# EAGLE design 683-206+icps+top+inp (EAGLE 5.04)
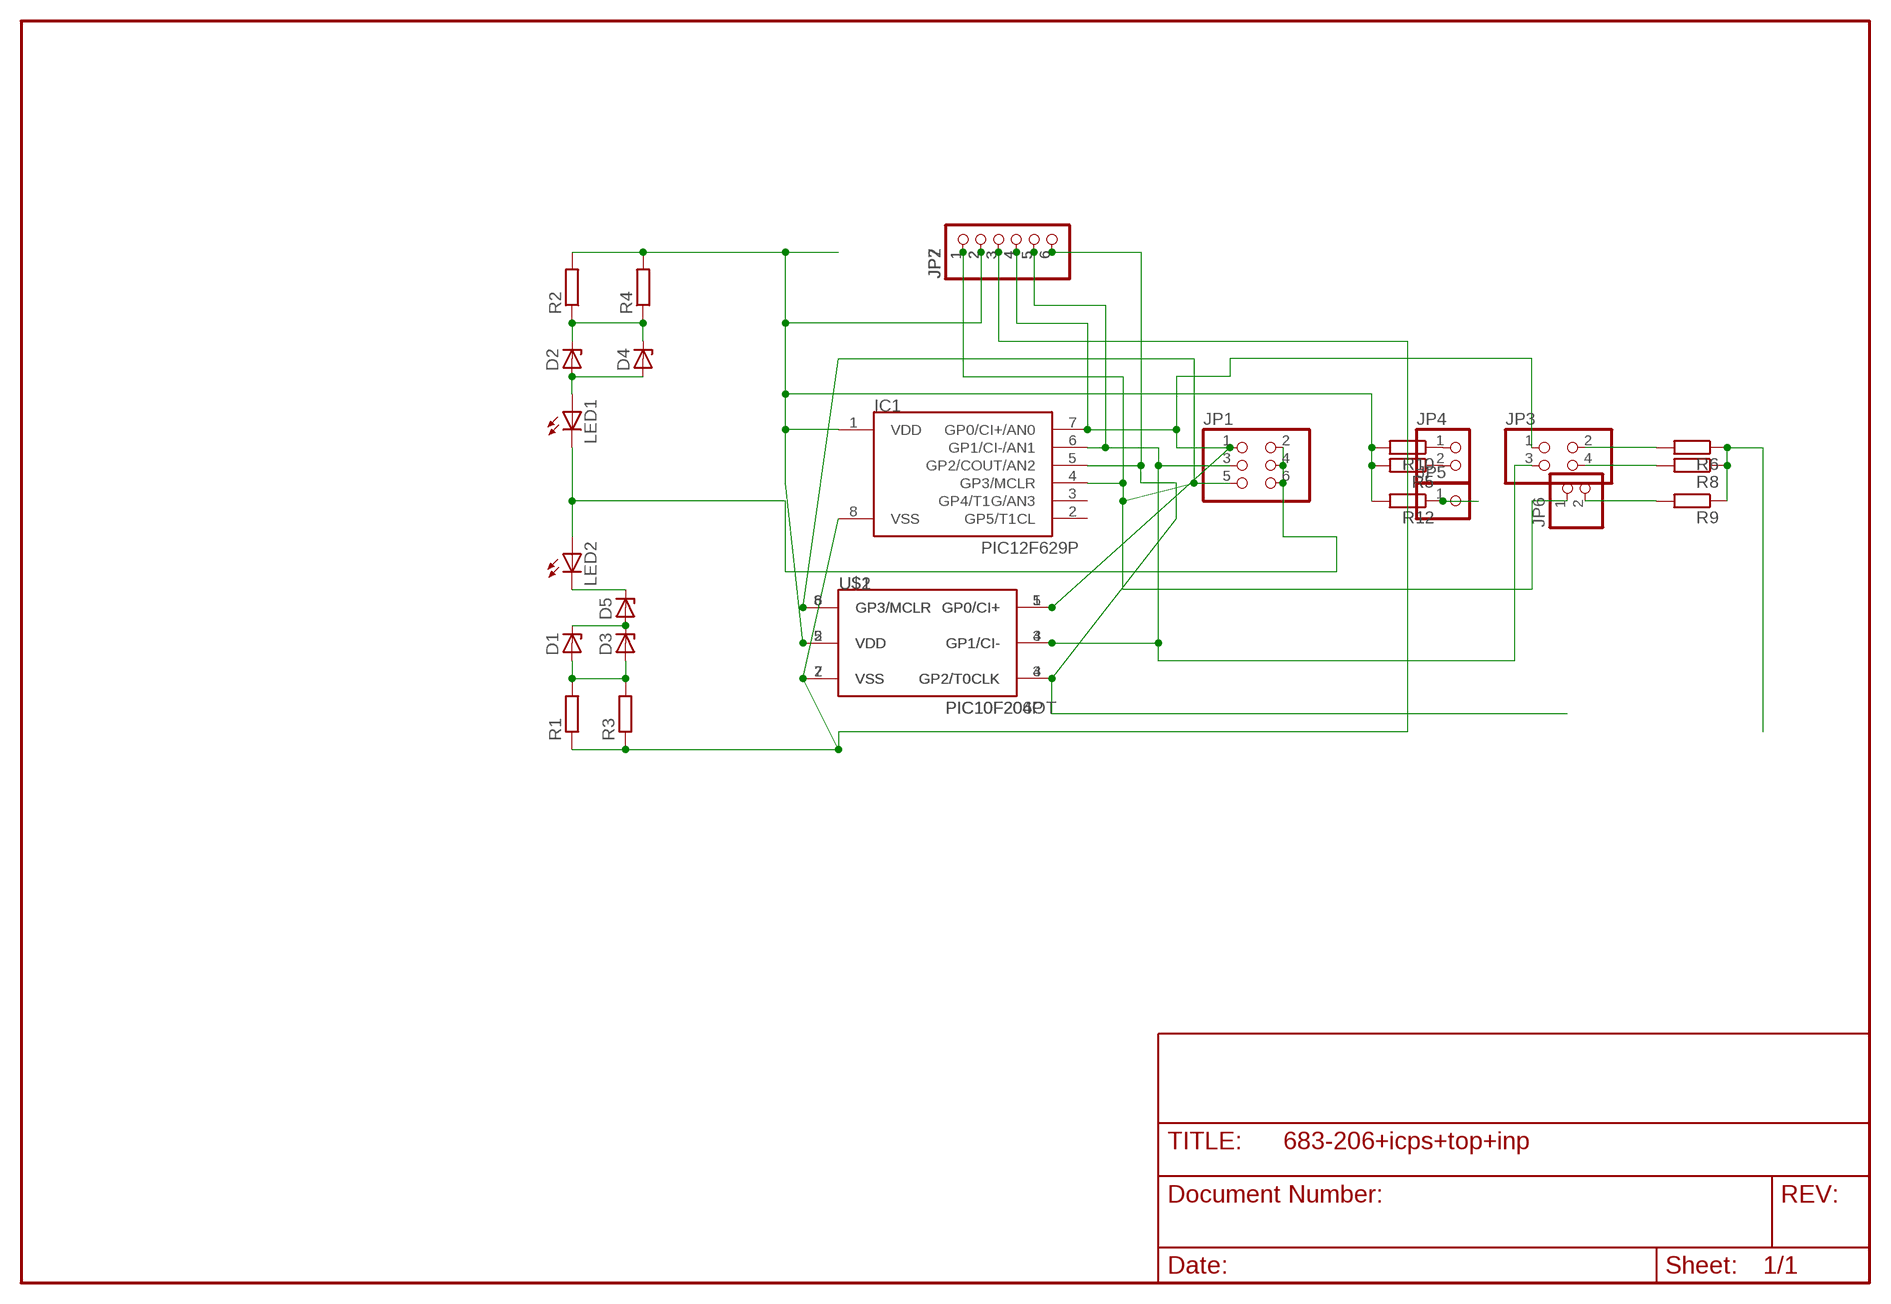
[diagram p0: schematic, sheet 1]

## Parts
D1  ZENER-DIODESOT23  [SOT23]
D2  ZENER-DIODESOT23  [SOT23]
D3  ZENER-DIODEZD-2.5  [ZDIO-2.5]
D4  ZENER-DIODEZD-2.5  [ZDIO-2.5]
D5  ZENER-DIODESOT23  [SOT23]
IC1  PIC12F629P  [DIL8]
JP1  PINHD-2X3  [2X03]
JP2  PINHD-1X6  [1X06]
JP3  PINHD-2X2  [2X02]
JP4  PINHD-1X2  [1X02]
JP5  PINHD-1X1  [1X01]
JP6  PINHD-1X2  [1X02]
JP7  PINHD-1X6  [1X06]
LED1  LED5MM  [LED5MM]
LED2  LED5MM  [LED5MM]
R1  R-EU_0204/2V  [0204V]
R2  R-EU_0204/2V  [0204V]
R3  R-EU_R1206  [R1206]
R4  R-EU_R1206  [R1206]
R5  R-EU_R1206  [R1206]
R6  R-EU_R1206  [R1206]
R8  R-EU_R1206  [R1206]
R9  R-EU_R1206  [R1206]
R10  R-EU_R1206  [R1206]
R12  R-EU_R1206  [R1206]
U$1  PIC10F206P  [DIL8]
U$2  PIC10F204OT  [SOT23-6]

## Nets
N$1: IC1.6(GP1/CI-/AN1) JP1.3 JP2.5 JP3.3 JP7.5 U$1.4(GP1/CI-) U$2.3(GP1/CI-)
N$2: D1.3(C) D3.C D5.1(A)
N$3: D1.1(A) D3.A R1.2 R3.2
N$4: JP1.2 JP1.4 JP1.6 LED1.K(C) LED2.A
N$5: IC1.8(VSS) JP2.3 JP7.3 R1.1 R3.1 U$1.7(VSS) U$2.2(VSS)
N$6: IC1.1(VDD) JP2.2 JP7.2 R2.2 R4.2 R5.2 R10.2 R12.2 U$1.2(VDD) U$2.5(VDD)
N$7: D2.1(A) D4.A LED1.A
N$8: D2.3(C) D4.C R2.1 R4.1
N$9: IC1.5(GP2/COUT/AN2) JP2.6 JP7.6 U$1.3(GP2/T0CLK) U$2.4(GP2/T0CLK)
N$10: IC1.4(GP3/MCLR) JP1.5 JP2.1 JP6.1 JP7.1 U$1.8(GP3/MCLR) U$2.6(GP3/MCLR)
N$11: D5.3(C) LED2.K(C)
N$13: IC1.7(GP0/CI+/AN0) JP1.1 JP2.4 JP3.1 JP7.4 U$1.5(GP0/CI+) U$2.1(GP0/CI+)
N$14: R6.1 R8.1 R9.1
N$15: JP4.2 R5.1
N$16: JP4.1 R10.1
N$18: JP5.1 R12.1
N$22: JP6.2 R9.2
N$24: JP3.4 R8.2
N$25: JP3.2 R6.2
Unconnected: IC1.2(GP5/T1CL) IC1.3(GP4/T1G/AN3)

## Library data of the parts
D1-D5 = diode-1:ZENER-DIODE: Z-Diode
IC1 = microchip-5:PIC12F6*: uPC nW 1k Program Flash memory 2x Timer Comparator 10b A/D converter/ 4xIN
JP1 = pinhead:PINHD-2X3: PIN HEADER
JP2 JP7 = pinhead:PINHD-1X6: PIN HEADER
JP3 = pinhead(2):PINHD-2X2: PIN HEADER
JP4 JP6 = pinhead(2):PINHD-1X2: PIN HEADER
JP5 = pinhead(2):PINHD-1X1: PIN HEADER
LED1 LED2 = led:LED: LED
R1-R6 R8-R10 R12 = rcl-2:R-EU_: RESISTOR, European symbol
U$1 U$2 = microchip-5:PIC10F2*: uPC nW 0,25/0,5k Program Flash memory Comparator

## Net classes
0 default: width 0.3 mm, drill 0.6 mm, clearance 0.2 mm
1 power: width 0.4 mm, drill 0.6 mm, clearance 0.2 mm

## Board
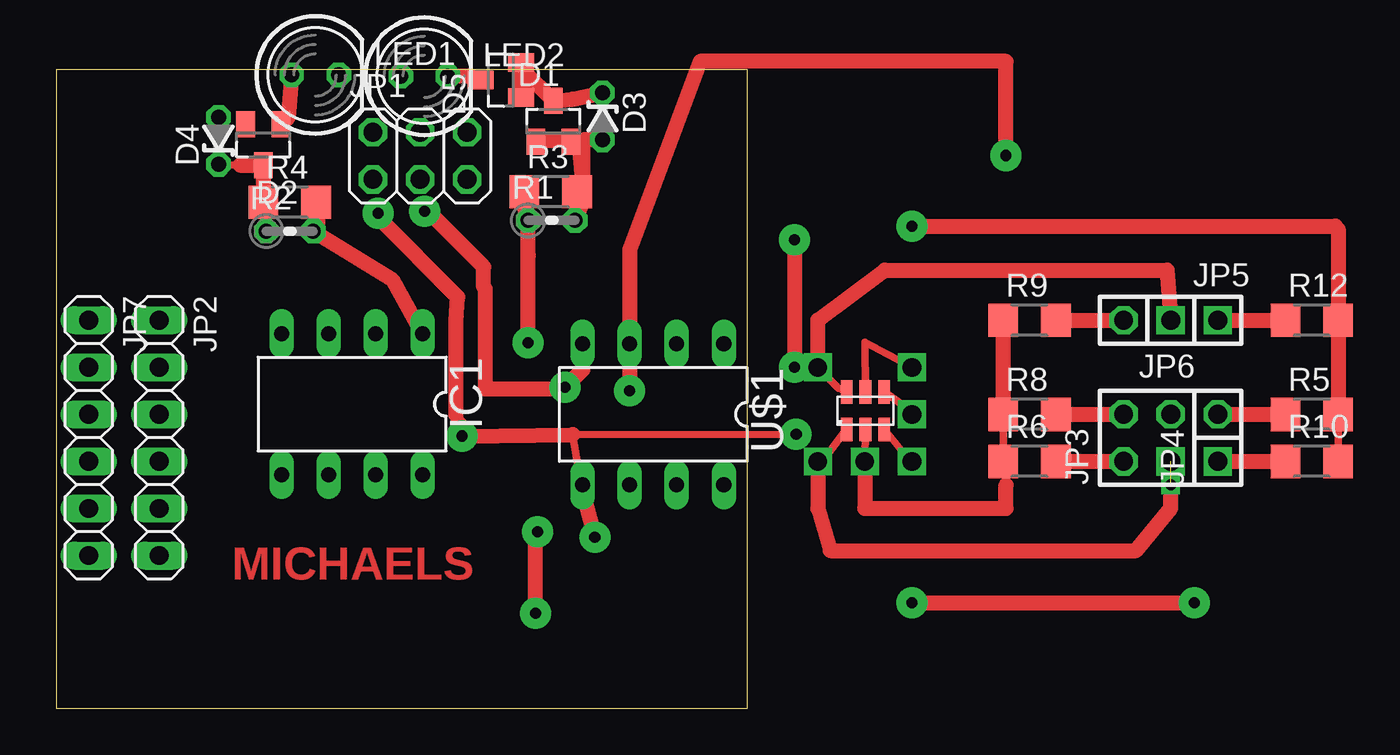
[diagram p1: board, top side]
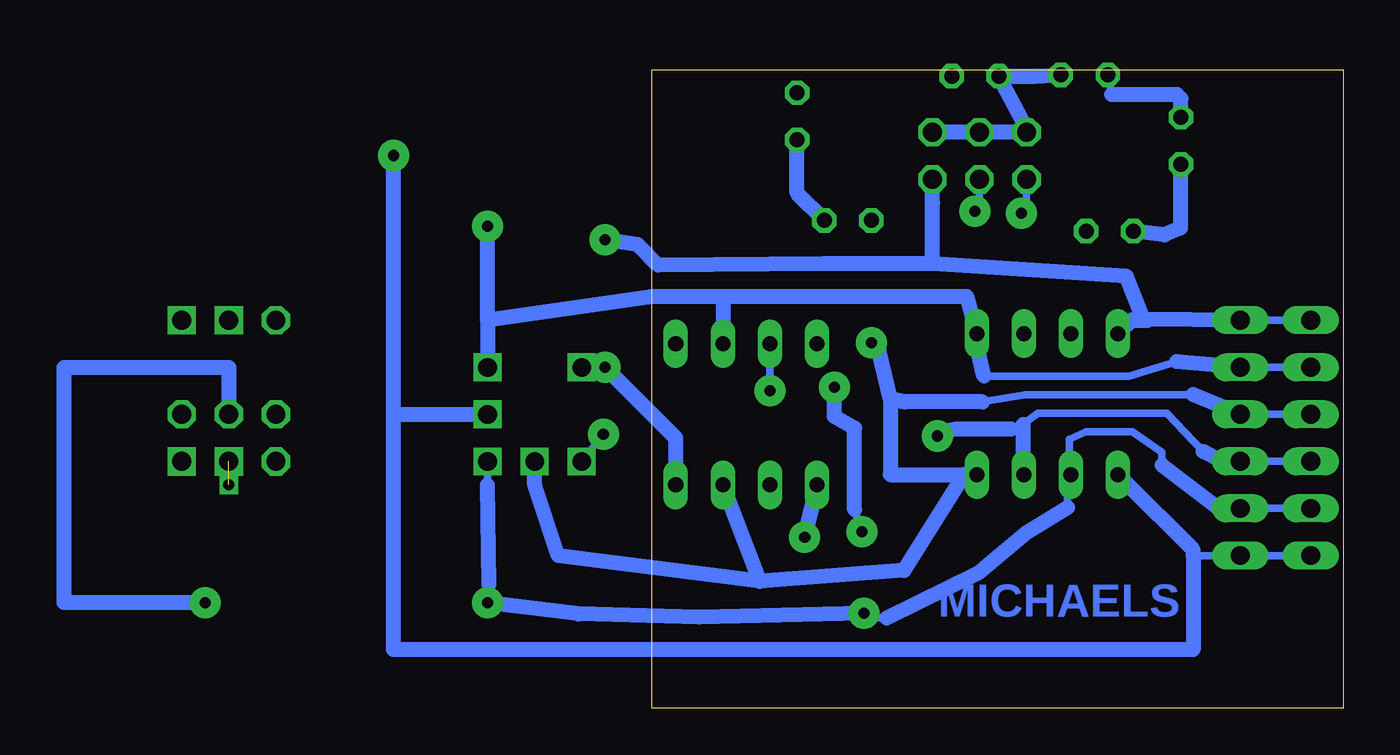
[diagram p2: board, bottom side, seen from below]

Size 37.3 x 34.48 mm. Coordinates in mm from the lower left corner, seen from the top.
Outline: 0,0 37.3,0 37.3,34.48 0,34.48 0,0
Copper layers (1*16): Top 0.035mm / dielectric 1.5mm / Bottom 0.035mm
Design rules "default": minimum track width 10mil, minimum drill 24mil, track to track 8mil, track to pad 8mil, pad to pad 8mil, via to via 8mil, smd to smd 8mil, copper to edge 40mil, drill to drill 8mil, minimum pad ring 10mil, minimum via ring 8mil, stop-mask expansion 4mil, vias tented up to drill 0mil, thermal gap 10mil

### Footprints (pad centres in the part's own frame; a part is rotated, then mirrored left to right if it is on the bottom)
SOT23 = smd 1 x 1.4: 1 -0.95,-1.1; 2 0.95,-1.1; 3 0,1.1
ZDIO-2.5 = drill 0.813 octagon: A 1.27,0; C -1.27,0
DIL8 = drill 0.813 long: 1 -3.81,-3.81; 2 -1.27,-3.81; 3 1.27,-3.81; 4 3.81,-3.81; 5 3.81,3.81; 6 1.27,3.81; 7 -1.27,3.81; 8 -3.81,3.81
2X03 = drill 1.016 octagon: 1 -2.54,-1.27; 2 -2.54,1.27; 3 0,-1.27; 4 0,1.27; 5 2.54,-1.27; 6 2.54,1.27
1X06 = drill 1.016 long: 1 -6.35,0; 2 -3.81,0; 3 -1.27,0; 4 1.27,0; 5 3.81,0; 6 6.35,0
2X02 = drill 1.016 square: 1 -1.27,-1.27 | drill 1.016 octagon: 2 -1.27,1.27; 3 1.27,-1.27; 4 1.27,1.27
1X02 = drill 1.016 square: 1 -1.27,0 | drill 1.016 octagon: 2 1.27,0
1X01 = drill 1.016 square: 1 0,0
LED5MM = drill 0.813 octagon: A -1.27,0; K 1.27,0
0204V = drill 0.813 octagon: 1 -1.27,0; 2 1.27,0
R1206 = smd 1.6 x 1.803: 1 -1.422,0; 2 1.422,0
SOT23-6 = smd 0.635 x 1.27: 1 -1.016,-1.016; 2 0,-1.016; 3 1.016,-1.016; 4 1.016,1.016; 5 0,1.016; 6 -1.016,1.016

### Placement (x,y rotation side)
D1  26.83,31.69 0 top
D2  11.17,30.41 180 top
D3  29.48,31.96 270 top
D4  8.75,30.63 90 top
D5  23.99,33.92 90 top
IC1  15.96,16.42 180 top
JP1  19.63,29.82 0 top
JP2  5.55,14.6 270 top
JP3  58.89,14.6 90 top  (outside the outline)
JP4  62.7,14.6 90 top  (outside the outline)
JP5  62.7,20.95 0 top  (outside the outline)
JP6  58.89,20.95 180 top  (outside the outline)
JP7  1.74,14.6 270 top
LED1  13.97,34.19 0 top
LED2  19.86,34.12 0 top
R1  26.74,26.33 0 top
R2  12.6,25.76 0 top
R3  26.69,27.88 0 top
R4  12.6,27.32 0 top
R5  67.78,15.87 0 top  (outside the outline)
R6  52.54,13.33 0 top  (outside the outline)
R8  52.54,15.87 0 top  (outside the outline)
R9  52.54,20.95 0 top  (outside the outline)
R10  67.78,13.33 0 top  (outside the outline)
R12  67.78,20.95 0 top  (outside the outline)
U$1  32.22,15.87 180 top
U$2  43.68,16.07 0 top  (outside the outline)

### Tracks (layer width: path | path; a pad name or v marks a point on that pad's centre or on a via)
N$1  (via drill 0.6 pad 1.68, 1)
  Top 0.406: U$2.3 45.7,13.82 v46.19,13.33 | 25.87,9.23 v25.97,9.53 | v27.47,17.33 27.37,17.23 | 20.07,26.83 v19.87,26.83 | 23.17,22.64 23.07,22.74
  Top 0.813: 23.17,22.64 23.17,17.23 27.37,17.23 | v25.87,5.13 25.87,9.23 | v46.19,5.71 v61.43,5.71 | U$1.4 28.41,18.27 v27.47,17.33 | 20.07,26.83 23.07,23.83 23.07,22.74
  Bottom 0.406: 6.74,10.79 JP2.5 JP7.5 | 9.78,13.13 9.78,13.83 11.38,14.93 13.88,14.93 14.78,14.53 14.78,12.7 IC1.6 14.88,12.42 14.88,10.83 | 46.19,12.06 v46.19,13.33 | v46.19,5.71 46.19,6.66 46.12,6.69 | v25.97,9.53 26.37,10.73 | 24.64,4.89 25.93,4.89 v25.87,5.13 | JP1.3 19.63,27.07 v19.87,26.83
  Bottom 0.813: 6.74,10.79 9.78,13.13 | 46.12,6.69 46.19,12.06 | 24.64,4.89 19.68,7.33 17.18,9.43 14.88,10.83 | 26.37,10.73 26.37,15.13 27.47,15.74 v27.47,17.33 | JP3.3 60.16,18.41 69.05,18.41 69.05,5.71 v61.43,5.71 | v25.87,5.13 34.77,4.93 41.29,5.1 v46.19,5.71
N$2
  Top 0.813: D5.1 25.16,34.43 D1.3 27.87,32.89 D3.C
N$3
  Top 0.813: 28.21,27.19 R3.2 28.41,27.33 R1.2 | D1.1 28.21,30.69 28.41,28.57 28.41,30.69 D3.A
  Bottom 0.813: D3.A 29.48,27.8 R1.2
N$4
  Bottom 0.406: JP1.2 17.09,31.35
  Bottom 0.813: LED1.K 16.58,34.12 LED2.A 17.09,31.35 | JP1.2 JP1.4 JP1.6
N$5  (via drill 0.6 pad 1.68, 1)
  Top 0.406: v43.65,13.33 U$2.2 | 51.27,12.06 51.12,12.21
  Top 0.813: R3.1 25.16,27.5 R1.1 25.47,24.43 v25.47,19.73 | 51.27,12.06 51.27,10.79 43.65,10.79 v43.65,13.33
  Bottom 0.406: 8.09,16.94 17.15,16.93 19.47,16.54 | 25.05,19.31 v25.47,19.73 | JP7.3 JP2.3
  Bottom 0.813: JP2.3 8.09,16.94 | 20.48,12.61 IC1.8 | 20.48,12.61 24.44,12.61 24.45,16.72 | 20.48,12.61 23.7,7.45 31.49,6.85 | 31.49,6.85 42.38,8.25 43.65,12.06 v43.65,13.33 | 19.47,16.54 23.63,16.54 23.84,16.57 24.45,16.72 | 31.49,6.85 U$1.7 | 24.45,16.72 25.05,19.31
N$6  (via drill 0.6 pad 1.68, 1)
  Top 0.406: U$2.5 43.67,19.76 v46.19,18.41 | 69.05,26.03 69.2,25.88 | R5.2 R10.2
  Top 0.813: IC1.1 18.17,23.1 R2.2 14.12,26.21 R4.2 | 69.2,25.88 R12.2 R5.2 | v46.19,26.03 69.05,26.03
  Bottom 0.406: 9,18.71 11.58,17.93 19.38,17.93 | 19.68,19.23 19.68,20.14 IC1.1 | JP7.2 JP2.2
  Bottom 0.813: JP2.2 9,18.71 | 19.38,17.93 19.68,19.23 | 46.19,20.95 v46.19,18.41 | 46.19,20.95 37.3,22.22 33.49,22.22 | 33.49,22.22 20.32,22.22 IC1.1 | 46.19,20.95 v46.19,26.03 | 33.49,22.22 U$1.2
N$7
  Top 0.813: LED1.A 12.5,31.87 D2.1
  Bottom 0.406: 8.75,32.91 8.97,33.13 | 12.49,33.13 LED1.A
  Bottom 0.813: D4.A 8.75,32.91 | 8.97,33.13 12.49,33.13
N$8
  Top 0.406: 11.14,27.84 R4.1 11.14,26.76 | D4.C 9.91,29.31
  Top 0.813: 11.14,26.76 D2.3 9.91,29.31
  Bottom 0.406: 8.77,29.35 D4.C
  Bottom 0.813: R2.1 9.64,25.56 8.77,25.93 8.77,29.35
N$9  (via drill 0.6 pad 1.68, 1)
  Top 0.406: U$2.4 45.7,16.36 v46.19,15.87
  Top 0.813: v51.27,29.84 51.27,34.92 34.76,34.92 30.95,24.76 U$1.3 v30.95,17.14
  Bottom 0.406: 8.09,8.55 8.09,8.25 JP2.6 JP7.6 | IC1.5 11.75,12.21 11.9,12.06 | U$1.3 v30.95,17.14
  Bottom 0.813: 51.27,15.87 v46.19,15.87 | 51.27,15.87 51.27,3.17 8.09,3.17 8.09,8.25 | 8.09,8.55 11.75,12.21 | 51.27,15.87 v51.27,29.84
N$10  (via drill 0.6 pad 1.68, 1)
  Top 0.406: U$2.6 42.23,17.29 v41.11,18.41
  Top 0.813: v39.84,25.29 v39.84,18.41 | v41.11,18.41 41.11,20.95 44.72,23.66 59.96,23.66 JP6.1
  Bottom 0.406: 10.58,20.93 8.66,20.95 JP2.1 JP7.1 | v39.84,18.41 v41.11,18.41
  Bottom 0.813: v39.84,25.29 38.07,25.03 36.98,23.93 28.01,24 22.16,24 | 22.16,24 11.69,23.31 10.79,20.99 JP2.1 | 10.58,20.93 11.45,20.93 IC1.4 11.43,20.95 10.63,20.95 | JP1.5 22.16,27.27 22.16,24 | U$1.8 36.03,14.6 v39.84,18.41
N$11
  Top 0.813: LED2.K 22.17,34.12 D5.3
N$13  (via drill 0.6, 0.6 pad 1.68, 1)  (1 unrouted)
  Top 0.406: U$2.1 41.53,13.55 v41.11,13.33 | v39.94,14.8 27.87,14.78 28.37,11.83 | 21.57,15.83 22.7,14.7 v21.9,14.7 | 17.37,26.5 v17.37,26.73
  Top 0.813: v21.9,14.7 27.87,14.78 | v60.16,12.06 60.16,10.79 58.29,8.52 41.78,8.52 41.11,10.79 v41.11,13.33 | 21.57,15.83 21.57,20.93 21.67,22.2 17.37,26.5 | 28.37,11.83 v29.07,9.23
  Bottom 0.406: 6.58,13.33 JP2.4 JP7.4 | 7.56,13.87 9.52,15.93 16.48,15.93 17.28,15.33 17.92,15.07 | 17.28,12.66 IC1.7 | v39.94,14.8 v41.11,13.33 | 28.37,12.02 U$1.5 | JP1.1 17.09,27.01 v17.37,26.73
  Bottom 0.813: 6.58,13.33 7.56,13.87 | 17.28,15.33 17.28,12.66 | v21.9,14.7 21.93,14.9 20.86,15.07 17.92,15.07 | v29.07,9.23 28.37,12.02
N$14
  Top 0.406: R6.1 R8.1
  Top 0.813: R8.1 R9.1
N$15
  Top 0.813: JP4.2 R5.1
N$16
  Top 0.406: R10.1 66.51,13.33
  Top 0.813: JP4.1 R10.1
N$18
  Top 0.813: JP5.1 R12.1
N$22
  Top 0.813: R9.2 JP6.2
N$24
  Top 0.813: R8.2 JP3.4
N$25
  Top 0.813: R6.2 JP3.2

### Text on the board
Top: MICHAELS
Bottom: MICHAELS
